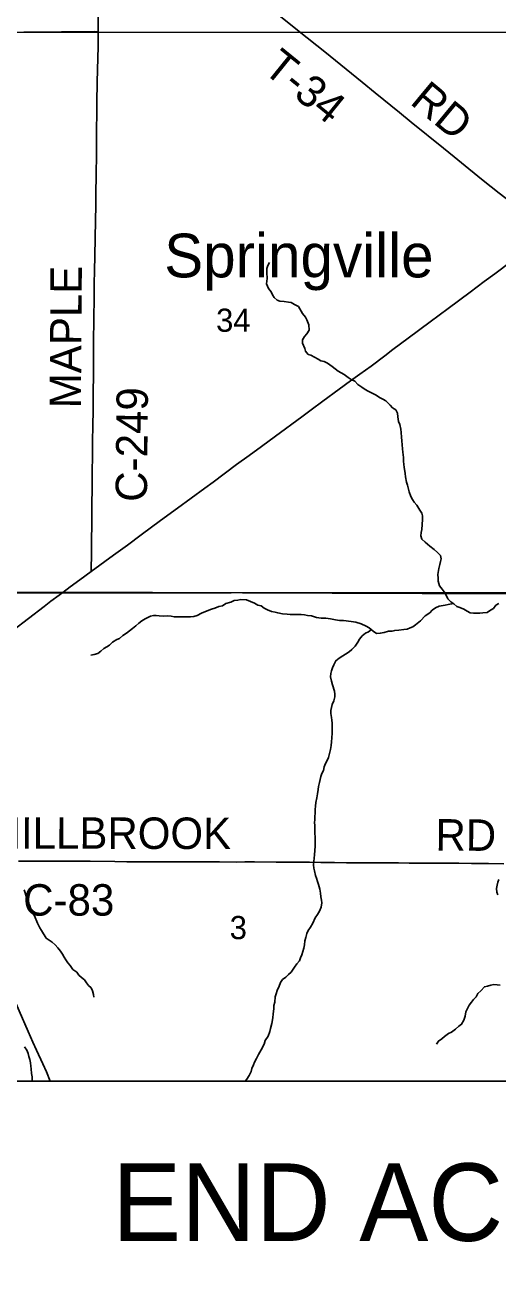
# Model space of a CAD drawing. Extents: x 0 to 34, y 0 to 22.
# Drawn here: x 6.615 to 7.469, y 17.158 to 19.442 of the extents above; entities that cross this region are included whole.
import ezdxf

# ---------------------------------------------------------------- set-up
doc = ezdxf.new("R2010")
doc.units = 0
for name, color, linetype in [('Default', 7, 'Continuous'), ('GM_X_County_Road', 7, 'Continuous'), ('GM_X_County_Road_Text', 7, 'Continuous'), ('GM_X_Minor_River', 7, 'Continuous'), ('GM_X_Section', 7, 'Continuous'), ('GM_X_Section_Text', 7, 'Continuous'), ('GM_X_State_Route', 7, 'Continuous'), ('GM_X_Township_Road', 7, 'Continuous'), ('GM_X_Township_Road_Text', 7, 'Continuous'), ('GM_X_Unincorporated_Text', 7, 'Continuous'), ('SH_Text', 7, 'Continuous')]:
    doc.layers.add(name, color=color, linetype=linetype)

msp = doc.modelspace()

# ---------------------------------------------------------------- linework, layer by layer
at = {"layer": 'Default'}
for points in [[(6.4755, 18.4174), (6.6827, 18.4182), (7.4947, 18.4149), (8.508, 18.4199), (8.7888, 18.4255), (8.8212, 18.4259), (8.9, 18.4271), (8.9, 20.9), (2.6032, 20.9)], [(8.9, 14.3696), (8.9, 18.4271), (8.8212, 18.4259), (8.7888, 18.4255), (8.508, 18.4199), (7.4947, 18.4149), (6.6827, 18.4182), (6.4755, 18.4174)]]:
    msp.add_lwpolyline(points, dxfattribs=at)
at = {"layer": 'GM_X_County_Road'}
for points in [[(6.7466, 19.4306), (6.7466, 19.4363), (6.7466, 19.4747), (6.7467, 19.4996), (6.7467, 19.5338), (6.7467, 19.5647), (6.7465, 19.6145), (6.7467, 19.6702), (6.747, 19.7154)], [(6.7343, 18.4554), (6.7343, 18.4687), (6.7344, 18.4779), (6.7347, 18.506), (6.7355, 18.5462), (6.7355, 18.5648), (6.7359, 18.6176), (6.7361, 18.6393), (6.7364, 18.661), (6.7367, 18.6891), (6.7373, 18.7201), (6.7376, 18.745), (6.7376, 18.77), (6.7379, 18.7824), (6.738, 18.8071), (6.7381, 18.8443), (6.7385, 18.8692), (6.7388, 18.9126), (6.7393, 18.95), (6.7395, 18.9745), (6.74, 18.9996), (6.7407, 19.0244), (6.7411, 19.0586), (6.7422, 19.1176), (6.7423, 19.1392), (6.7428, 19.1702), (6.7437, 19.2108), (6.7437, 19.2325), (6.7438, 19.2574), (6.7441, 19.2791), (6.7443, 19.3006), (6.7451, 19.341), (6.7457, 19.3596), (6.7464, 19.3844), (6.7466, 19.4019), (6.7467, 19.4237), (6.7466, 19.4306)], [(6.6597, 17.5349), (6.6531, 17.5517), (6.6469, 17.5659), (6.6353, 17.591), (6.6286, 17.6054), (6.6203, 17.6244), (6.6037, 17.6616), (6.5904, 17.6928), (6.5774, 17.7243), (6.5699, 17.7425), (6.5635, 17.7581), (6.5488, 17.7957), (6.5406, 17.8156), (6.533, 17.8326), (6.5144, 17.872), (6.5011, 17.9), (6.4959, 17.9113), (6.4922, 17.9198), (6.4891, 17.9279), (6.4879, 17.9317)], [(6.6029, 17.9324), (6.6277, 17.9324), (6.6463, 17.9323), (6.6743, 17.9324), (6.6984, 17.9324), (6.7138, 17.9324), (6.7325, 17.9321), (6.7766, 17.9315), (6.7984, 17.9312), (6.8263, 17.931), (6.8387, 17.931), (6.8542, 17.931), (6.8853, 17.9308), (6.907, 17.9309), (6.9412, 17.9309), (6.966, 17.9309), (6.9971, 17.9307), (7.0117, 17.9308), (7.0295, 17.9308), (7.0685, 17.9305), (7.0871, 17.9305), (7.1112, 17.9303), (7.1291, 17.9302), (7.1492, 17.9298), (7.1616, 17.9297), (7.174, 17.9296), (7.1959, 17.9294), (7.2204, 17.9293), (7.2351, 17.9291), (7.2477, 17.9293), (7.2902, 17.9289), (7.3092, 17.9286), (7.3332, 17.9284), (7.3619, 17.9284), (7.3773, 17.9283), (7.3991, 17.9283), (7.4217, 17.9282), (7.4526, 17.9278), (7.4805, 17.9274)]]:
    msp.add_lwpolyline(points, dxfattribs=at)
at = {"layer": 'GM_X_Minor_River'}
for points in [[(7.3626, 18.461), (7.3649, 18.4679), (7.366, 18.4732), (7.3668, 18.4785), (7.366, 18.4842), (7.3606, 18.4899), (7.3545, 18.4952), (7.3465, 18.5013), (7.3381, 18.5086), (7.3324, 18.5139), (7.3304, 18.52), (7.3312, 18.5257), (7.3323, 18.5314), (7.3334, 18.5496), (7.3334, 18.5557), (7.3319, 18.561), (7.3288, 18.5664), (7.323, 18.5751), (7.3181, 18.5804), (7.315, 18.5854), (7.3123, 18.5907), (7.3092, 18.5995), (7.3062, 18.6113), (7.3046, 18.6166), (7.3027, 18.6265), (7.3019, 18.6322), (7.3, 18.6436), (7.2996, 18.6489), (7.2992, 18.655), (7.2988, 18.6614), (7.2976, 18.671), (7.2969, 18.677), (7.2961, 18.6915), (7.2953, 18.6983), (7.2949, 18.7067), (7.2941, 18.7124), (7.2926, 18.7208), (7.2902, 18.7265), (7.2887, 18.7348), (7.2879, 18.7417), (7.2849, 18.7474), (7.2791, 18.7508), (7.2749, 18.7558), (7.2669, 18.7634), (7.2615, 18.7668), (7.2558, 18.7695), (7.2497, 18.774), (7.2424, 18.7778), (7.2348, 18.7813), (7.2298, 18.7843), (7.2233, 18.7881), (7.2164, 18.7934), (7.2107, 18.7992), (7.2046, 18.8022), (7.1989, 18.806), (7.1916, 18.8113), (7.1809, 18.8174), (7.1755, 18.8216), (7.1698, 18.8258), (7.1614, 18.8319), (7.1553, 18.8345), (7.1495, 18.8361), (7.1446, 18.8391), (7.1316, 18.846), (7.1266, 18.8475), (7.122, 18.8532), (7.1205, 18.8585), (7.1163, 18.868), (7.1163, 18.8741), (7.1197, 18.8798), (7.1239, 18.8848), (7.1284, 18.8916), (7.128, 18.9007), (7.1242, 18.9099), (7.1215, 18.9148), (7.1165, 18.9217), (7.1089, 18.9338), (7.1016, 18.938), (7.0959, 18.9411), (7.0909, 18.9422), (7.0829, 18.943), (7.0753, 18.9437), (7.0703, 18.9453), (7.0653, 18.9502), (7.0623, 18.9551), (7.0599, 18.9605), (7.0546, 18.9669), (7.0511, 18.9749), (7.0523, 18.9844), (7.0519, 18.9958), (7.0515, 19.0027), (7.0533, 19.008), (7.0568, 19.0137)], [(7.4712, 18.3975), (7.4662, 18.3948), (7.4616, 18.3883), (7.4563, 18.3853), (7.4502, 18.3815), (7.4426, 18.3807), (7.4372, 18.3804), (7.4254, 18.3804), (7.4197, 18.3808), (7.4143, 18.3838), (7.4078, 18.3872), (7.401, 18.3903), (7.3956, 18.3922), (7.3903, 18.3971), (7.3845, 18.4009), (7.3792, 18.4062), (7.3765, 18.4112), (7.3726, 18.4184), (7.3688, 18.4237), (7.3638, 18.4295), (7.3615, 18.4382), (7.3615, 18.4435), (7.3611, 18.45), (7.3626, 18.461)], [(7.3892, 18.3978), (7.3796, 18.3956), (7.3742, 18.3945), (7.3636, 18.3929), (7.3571, 18.3895), (7.351, 18.3857), (7.3464, 18.3808), (7.338, 18.3755), (7.33, 18.3664), (7.3209, 18.3591), (7.3159, 18.3557), (7.311, 18.3538), (7.3053, 18.3515), (7.2995, 18.3504), (7.2904, 18.3496), (7.2831, 18.3489), (7.2782, 18.3477), (7.2717, 18.3474), (7.2637, 18.3455), (7.2568, 18.344), (7.2503, 18.3432), (7.2442, 18.3478), (7.2369, 18.3535), (7.2312, 18.3569), (7.2224, 18.3611), (7.2125, 18.3641), (7.2045, 18.3653), (7.1907, 18.3668), (7.1835, 18.3672), (7.1758, 18.3683), (7.1671, 18.3699), (7.1583, 18.371), (7.1503, 18.3714), (7.1415, 18.3725), (7.1323, 18.3752), (7.1251, 18.376), (7.1197, 18.3771), (7.1136, 18.3779), (7.0942, 18.3779), (7.0888, 18.3783), (7.08, 18.379), (7.0716, 18.3806), (7.0667, 18.3821), (7.0602, 18.3832), (7.0529, 18.3859), (7.0468, 18.3893), (7.0418, 18.3935), (7.0353, 18.3947), (7.0292, 18.3981), (7.0223, 18.4015), (7.0147, 18.4042), (7.0048, 18.4046), (6.9994, 18.4038), (6.9926, 18.403), (6.9869, 18.4), (6.9777, 18.3974), (6.9716, 18.3936), (6.9647, 18.392), (6.9575, 18.389), (6.9518, 18.3871), (6.9438, 18.3841), (6.9339, 18.3799), (6.9255, 18.3761), (6.9198, 18.3742), (6.914, 18.3738), (6.9041, 18.3738), (6.8957, 18.3734), (6.89, 18.3734), (6.8843, 18.3738), (6.8785, 18.3746), (6.8713, 18.3754), (6.864, 18.375), (6.8572, 18.3754), (6.8518, 18.3757), (6.8465, 18.3758), (6.8411, 18.3746), (6.832, 18.3701), (6.8255, 18.3663), (6.8202, 18.3621), (6.8148, 18.3575), (6.8091, 18.3526), (6.8034, 18.348), (6.7977, 18.3438), (6.7912, 18.3397), (6.7855, 18.3347), (6.7802, 18.3324), (6.7725, 18.3275), (6.7672, 18.3226), (6.7623, 18.3191), (6.7569, 18.3161), (6.7516, 18.3115), (6.7459, 18.3074), (6.7394, 18.3058), (6.7333, 18.3043)], [(7.2414, 18.35), (7.2408, 18.3504), (7.2354, 18.3466), (7.2305, 18.344), (7.2244, 18.339), (7.2191, 18.333), (7.2164, 18.328), (7.2118, 18.3204), (7.2054, 18.3147), (7.2004, 18.3101), (7.1939, 18.306), (7.189, 18.3029), (7.1825, 18.2991), (7.1768, 18.2942), (7.173, 18.2866), (7.1703, 18.2813), (7.1688, 18.2763), (7.1673, 18.271), (7.1669, 18.2653), (7.1685, 18.2573), (7.1704, 18.2508), (7.1742, 18.2394), (7.1746, 18.2341), (7.1746, 18.2288), (7.1728, 18.2219), (7.1701, 18.2151), (7.1686, 18.2098), (7.1678, 18.2045), (7.1678, 18.1991), (7.1686, 18.1919), (7.1694, 18.1866), (7.1698, 18.1816), (7.1702, 18.1763), (7.1702, 18.1706), (7.1698, 18.1634), (7.1691, 18.155), (7.1687, 18.1478), (7.1684, 18.1409), (7.1669, 18.1337), (7.165, 18.1265), (7.1631, 18.1197), (7.1612, 18.114), (7.1581, 18.1086), (7.1555, 18.1029), (7.154, 18.0961), (7.1513, 18.0904), (7.1494, 18.0851), (7.1483, 18.0797), (7.1468, 18.0744), (7.1453, 18.0668), (7.1445, 18.0619), (7.1434, 18.0539), (7.1423, 18.0467), (7.1404, 18.0383), (7.1396, 18.0315), (7.1393, 18.0254), (7.1389, 18.0185), (7.1385, 18.0136), (7.1385, 18.0071), (7.1382, 18.0022), (7.1386, 17.9965), (7.1386, 17.9816), (7.139, 17.9767), (7.139, 17.9596), (7.1387, 17.9512), (7.1379, 17.9436), (7.1376, 17.9379), (7.1368, 17.9314), (7.1361, 17.9254), (7.1368, 17.9197), (7.138, 17.9147), (7.1399, 17.9063), (7.1415, 17.9014), (7.1434, 17.8953), (7.1453, 17.89), (7.1476, 17.8816), (7.1488, 17.8744), (7.1496, 17.8679), (7.1507, 17.8618), (7.1511, 17.8569), (7.15, 17.8493), (7.1469, 17.8421), (7.1435, 17.836), (7.1393, 17.8299), (7.1348, 17.8204), (7.1306, 17.8132), (7.1268, 17.8071), (7.1241, 17.8014), (7.1222, 17.7942), (7.1207, 17.7885), (7.12, 17.7813), (7.1185, 17.7748), (7.117, 17.7691), (7.1151, 17.763), (7.1128, 17.7577), (7.1109, 17.752), (7.1063, 17.7467), (7.1021, 17.741), (7.0957, 17.7315), (7.0907, 17.7277), (7.0862, 17.7227)], [(7.4712, 17.8993), (7.4693, 17.894), (7.4682, 17.889), (7.467, 17.8826), (7.4678, 17.8765), (7.4697, 17.8716)], [(6.6126, 17.8804), (6.6179, 17.8656), (6.6206, 17.8572), (6.6229, 17.8519), (6.6248, 17.8454), (6.6271, 17.8401), (6.6314, 17.8333), (6.6367, 17.8203), (6.6413, 17.812), (6.644, 17.807), (6.6525, 17.7933), (6.6632, 17.7861), (6.6689, 17.7808), (6.6735, 17.7754), (6.6788, 17.7697), (6.6823, 17.764), (6.685, 17.7591), (6.688, 17.7541), (6.6919, 17.7488), (6.6961, 17.7435), (6.7007, 17.7366), (6.7079, 17.7317), (6.7118, 17.7264), (6.7167, 17.7218), (6.7217, 17.718), (6.7255, 17.7127), (6.729, 17.7077), (6.734, 17.7035), (6.7366, 17.6978), (6.7382, 17.6914), (6.739, 17.6864)], [(7.0862, 17.7227), (7.0804, 17.7185), (7.0763, 17.7132), (7.074, 17.7067), (7.0706, 17.6984), (7.0687, 17.6927), (7.0668, 17.6874), (7.066, 17.6775), (7.0645, 17.6714), (7.0642, 17.6653), (7.0634, 17.6562), (7.0627, 17.6493), (7.0608, 17.6391), (7.0585, 17.6299), (7.057, 17.6246), (7.054, 17.6163), (7.0486, 17.6083), (7.0468, 17.6014), (7.0414, 17.5915), (7.0369, 17.5828), (7.0331, 17.576), (7.0297, 17.5691), (7.0274, 17.5642), (7.0247, 17.5577), (7.0232, 17.5524), (7.0198, 17.5448), (7.0156, 17.5387), (7.0125, 17.5349)], [(7.4739, 17.7084), (7.4686, 17.7088), (7.4621, 17.7092), (7.4571, 17.7084), (7.4507, 17.7065), (7.4453, 17.7054), (7.4388, 17.6978), (7.4335, 17.6932), (7.4301, 17.6872), (7.4255, 17.6822), (7.4221, 17.6773), (7.4179, 17.6719), (7.4149, 17.6662), (7.4118, 17.6598), (7.4103, 17.6522), (7.4081, 17.6453), (7.4039, 17.6377), (7.3989, 17.6343), (7.3928, 17.6286), (7.386, 17.6233), (7.3803, 17.621), (7.3734, 17.6157), (7.3685, 17.6115), (7.3624, 17.6073), (7.3589, 17.6016)], [(6.6136, 17.5967), (6.6174, 17.5907), (6.6201, 17.5846), (6.6213, 17.5796), (6.6232, 17.5739), (6.6244, 17.5678), (6.6251, 17.5621), (6.6255, 17.5572), (6.6263, 17.5484), (6.6271, 17.5424), (6.6275, 17.5367), (6.6273, 17.5349)]]:
    msp.add_lwpolyline(points, dxfattribs=at)
at = {"layer": 'GM_X_Section'}
for points in [[(6.4874, 20.4413), (7.5127, 20.4367), (7.5091, 19.4296), (6.4824, 19.4291)], [(6.4824, 19.4291), (7.5091, 19.4296), (7.4947, 18.4172), (6.4793, 18.4161)], [(7.5121, 17.5349), (7.5102, 18.4173), (7.4947, 18.4172), (6.4793, 18.4161), (6.4931, 17.5349)]]:
    msp.add_lwpolyline(points, close=True, dxfattribs=at)
at = {"layer": 'GM_X_State_Route'}
for points in [[(6.6829, 18.4176), (6.6962, 18.4275), (6.7137, 18.4404), (6.7343, 18.4554), (6.7746, 18.4847), (6.7995, 18.5032), (6.8246, 18.5216), (6.8593, 18.5473), (6.8901, 18.5697), (6.9399, 18.6059), (6.9549, 18.617), (6.9972, 18.6485), (7.0197, 18.665), (7.0423, 18.6815), (7.0674, 18.6999), (7.115, 18.7347), (7.1319, 18.7477), (7.1529, 18.7632), (7.1827, 18.7845), (7.2031, 18.7998), (7.22, 18.812), (7.2402, 18.8266), (7.2651, 18.8451), (7.2799, 18.8564), (7.3074, 18.8768), (7.3473, 18.9063), (7.3798, 18.9303), (7.4194, 18.96), (7.4451, 18.979), (7.4643, 18.9932), (7.4937, 19.0152)], [(6.4843, 18.2673), (6.4906, 18.2721), (6.5129, 18.289), (6.5378, 18.3076), (6.56, 18.3245), (6.5922, 18.349), (6.6489, 18.3923), (6.6613, 18.4016), (6.6763, 18.4127), (6.6829, 18.4176)]]:
    msp.add_lwpolyline(points, dxfattribs=at)
at = {"layer": 'GM_X_Township_Road'}
for points in [[(7.0766, 19.4579), (7.1105, 19.4307), (7.1565, 19.3941), (7.2244, 19.3395), (7.248, 19.3199), (7.2917, 19.2848), (7.3131, 19.2669), (7.3712, 19.2203), (7.3905, 19.2046), (7.4169, 19.1827), (7.4432, 19.1614), (7.4723, 19.1385), (7.4923, 19.1231), (7.503, 19.1154)], [(6.6122, 19.4295), (6.6463, 19.4298), (6.6805, 19.43), (6.7053, 19.4303), (6.7208, 19.4305), (6.7393, 19.4306), (6.7421, 19.4305), (6.7466, 19.4306)]]:
    msp.add_lwpolyline(points, dxfattribs=at)
at = {"layer": 'SH_Text'}
msp.add_lwpolyline([(6.4908, 17.5349), (8.7107, 17.5349), (8.7107, 16.8178), (6.4908, 16.8178)], close=True, dxfattribs=at)

# ---------------------------------------------------------------- texts
at = {"layer": 'GM_X_County_Road_Text'}
for s, rotation, p in [('MAPLE', 89.5953, (6.7155, 18.7501)), ('C-249', 89.4515, (6.8349, 18.5811)), ('MILLBROOK', 359.885, (6.5438, 17.9549)), ('RD', 359.5091, (7.3566, 17.9515)), ('C-83', 0, (6.6112, 17.8338))]:
    msp.add_text(s, height=0.05682, rotation=rotation, dxfattribs=at).set_placement(p)
at = {"layer": 'GM_X_Section_Text'}
for s, height, p in [('34', 0.04186, (6.96, 18.8884)), ('3', 0.0419, (6.9846, 17.7913))]:
    msp.add_text(s, height=height, rotation=0, dxfattribs=at).set_placement(p)
at = {"layer": 'GM_X_Township_Road_Text'}
for s, rotation, p in [('T-34', 321.0091, (7.0425, 19.3592)), ('RD', 320.2575, (7.3088, 19.3014))]:
    msp.add_text(s, height=0.05682, rotation=rotation, dxfattribs=at).set_placement(p)
at = {"layer": 'GM_X_Unincorporated_Text'}
msp.add_text('Springville', height=0.078977, rotation=0, dxfattribs=at).set_placement((6.8662, 18.9867))
at = {"layer": 'SH_Text'}
msp.add_text('END ACQUISTION', height=0.14, dxfattribs=at).set_placement((6.7718, 17.2463))

doc.saveas('drawing.dxf')
